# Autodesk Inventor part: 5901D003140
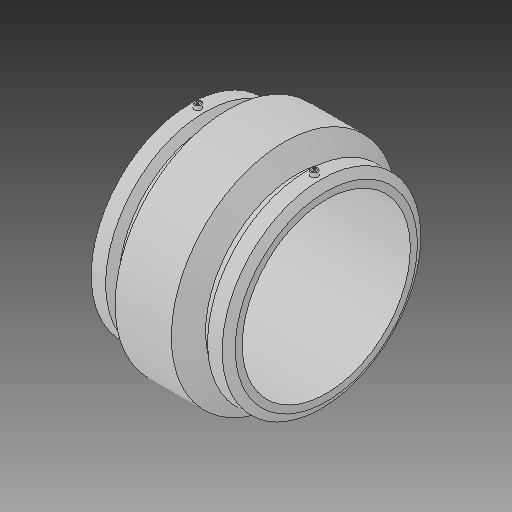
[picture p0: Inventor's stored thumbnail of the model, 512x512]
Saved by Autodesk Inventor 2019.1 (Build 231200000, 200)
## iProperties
Created: 2017-06
Part Number: 5901D003140
Material: Generic
Description: PLASSON COUPLER 14''DIPS
Document SubType Name: Modeling
Designer: KIM
Mass: 96874 g
Surface Area: 34549.7 cm^2
Volume: 96874 cm^3
Density: 1 g/cm^3
Appearance: Default
Author: KIM
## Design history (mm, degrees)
derived "5901D.ipt"
feature "Solid1::5901D.ipt"
tag "TaggingFeature1"
body "Solid1"
other parameters: "d13" = 295.91, "d15" = 144.78, "d16" = 144.78, "d17" = 354, "d22" = 435.864, "d23" = 474.98, "d24" = 383.56032, "d25" = 150 deg, "d26" = 118.364, "d27" = 120 deg, "d29" = 217.932, "d35" = 15, "d39" = 0, "d40" = 4, "d41" = 14, "d42" = 0, "d44" = 50.673, "d45" = 354, "d47" = 0, "d48" = 209.21472, "d49" = 50.673, "d50" = 60 deg, "d57" = 65.786, "d58" = 50.673, "d62" = 354, "d65" = 282.448, "d67" = 5.27613, "d68" = 21.15863, "d69" = 21.80789, "d70" = 21.71015, "d71" = 20.5722, "d72" = 20.71531, "d73" = 561.2638, "d76" = 118.364, "d77" = 383.56032, "d_" = 354, "L_" = 295.91, "L_1" = 144.78, "D_" = 474.98, "A_" = 217.932, "A_1" = 25.4, "d60" = 187.96
